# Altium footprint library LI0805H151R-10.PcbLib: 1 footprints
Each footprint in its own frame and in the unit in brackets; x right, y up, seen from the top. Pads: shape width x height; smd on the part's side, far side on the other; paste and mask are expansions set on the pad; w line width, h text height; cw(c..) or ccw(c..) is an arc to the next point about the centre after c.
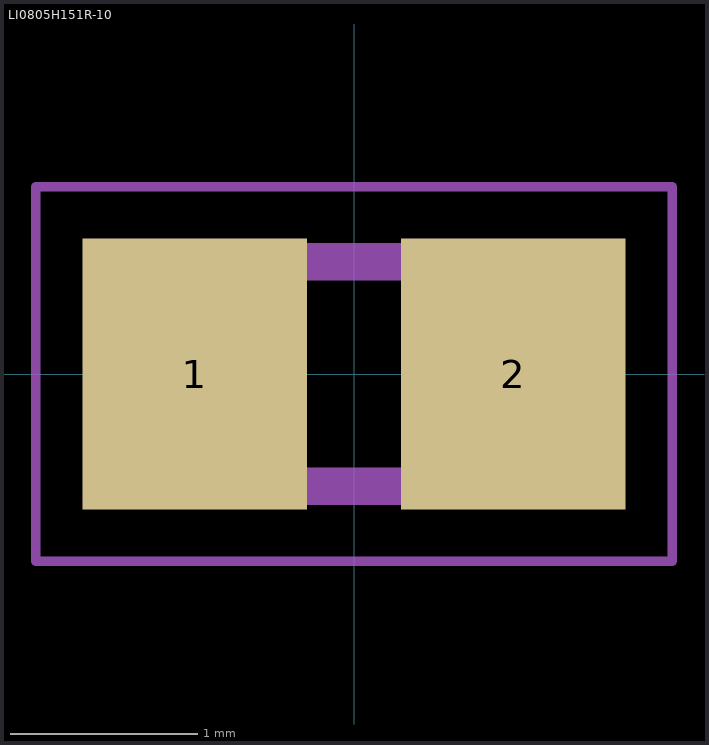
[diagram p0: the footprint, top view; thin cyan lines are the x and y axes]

## LI0805H151R-10 [mm]
pads (2):
  rect 1.2x1.45 smd: 1(-0.85,0) 2(0.85,0)
Mechanical 13:
  region: 1,-0.6 0.5,-0.6 0.5,0.6 1,0.6
  region: -0.5,-0.601 -1.001,-0.601 -1.001,0.6 -0.5,0.6
  lines w0.2: -1,-0.6 -1,0.6 1,0.6 1,-0.6 -1,-0.6
Mechanical 15:
  lines w0.05: -1.7,-1 -1.7,1 1.7,1 1.7,-1 -1.7,-1
3D body "LI0805H151R-10.STEP": height 1.15, standoff 0.05, extent -1,-0.625 1,0.625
